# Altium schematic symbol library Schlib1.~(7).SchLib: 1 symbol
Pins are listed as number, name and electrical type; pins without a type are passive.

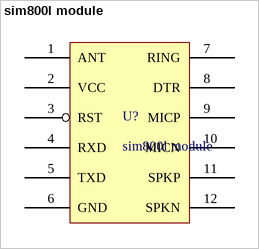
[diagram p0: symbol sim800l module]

## sim800l module
designator U?
footprint sim800l module
pins: 1 ANT, 2 VCC (power), 3 RST, 4 RXD, 5 TXD, 6 GND (power), 7 RING, 8 DTR, 9 MICP, 10 MICN, 11 SPKP, 12 SPKN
